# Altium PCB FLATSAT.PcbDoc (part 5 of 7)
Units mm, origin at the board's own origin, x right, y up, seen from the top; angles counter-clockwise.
Board outline 430 x 350 mm, 5 copper layers (Top Layer, Internal Plane 1, Internal Plane 2, DELETEME, Bottom Layer); 808 components, 852 nets, 6407 pads, 939 vias.
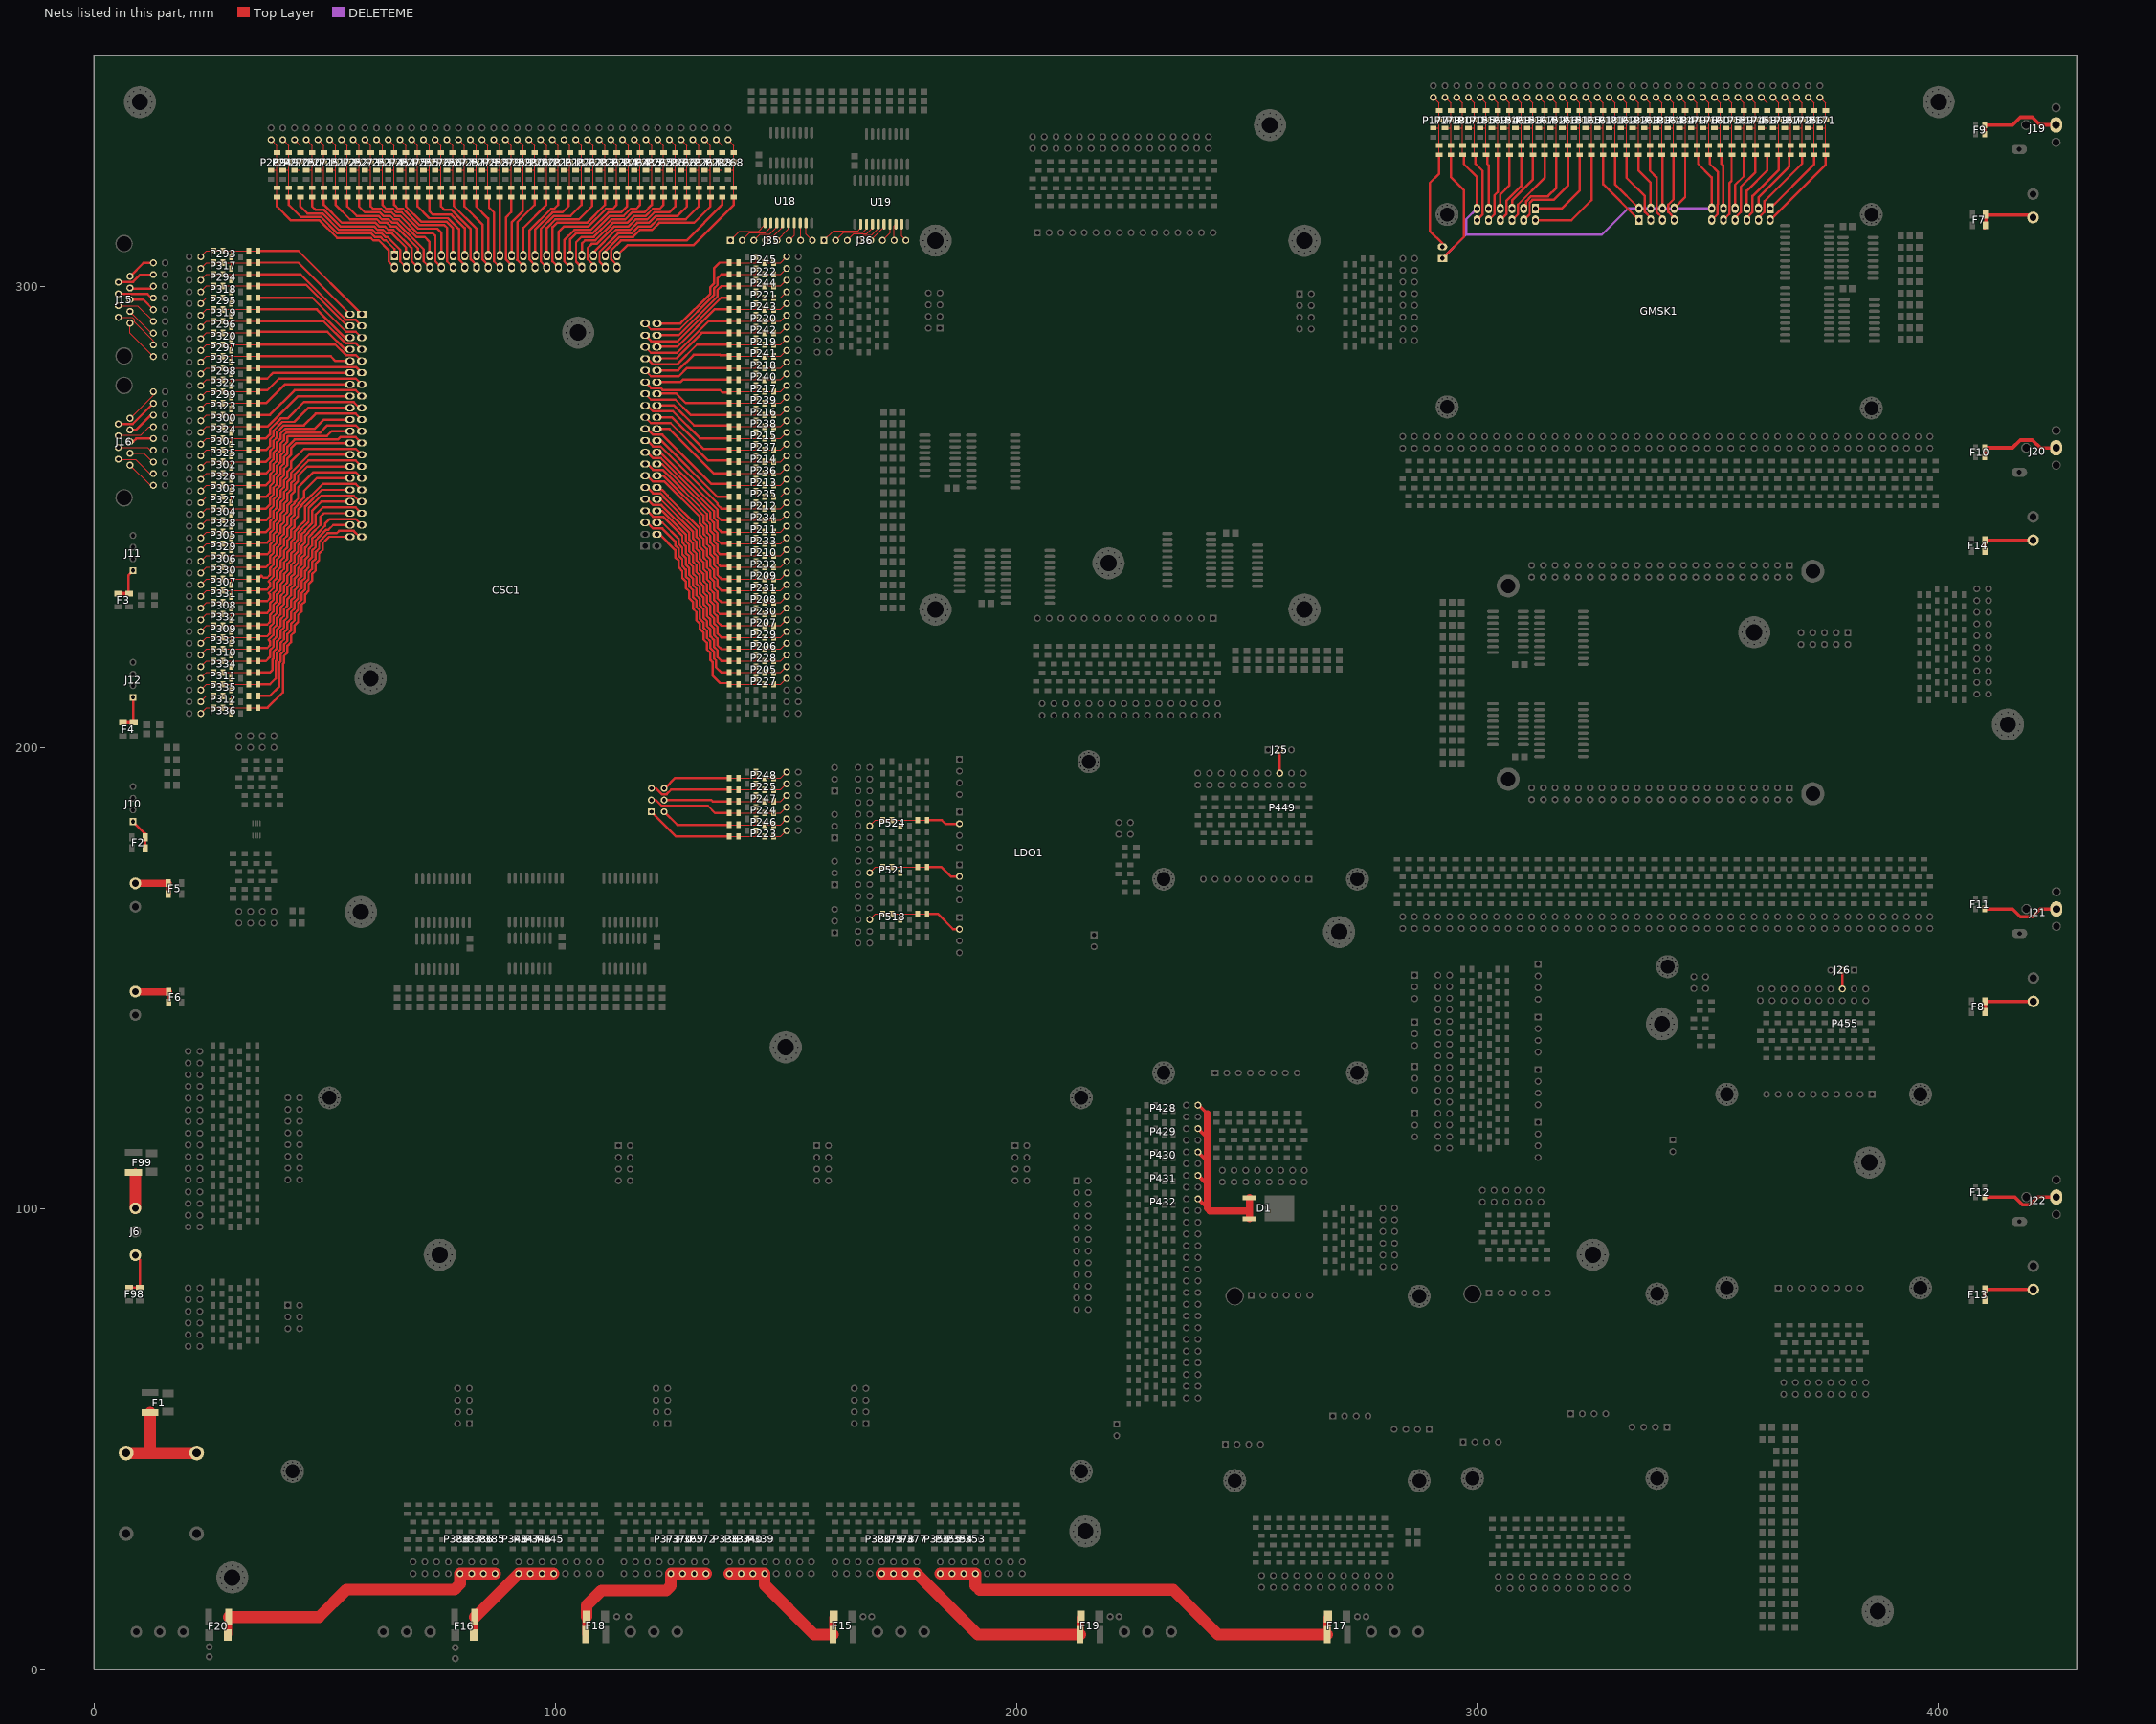
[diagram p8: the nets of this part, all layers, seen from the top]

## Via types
v1: diameter 1.016, hole 0.508, Top Layer to Bottom Layer, 541 vias
v2: diameter 0.6, hole 0.3, Top Layer to Bottom Layer, 214 vias
v3: diameter 1.27, hole 0.711, Top Layer to Bottom Layer, 147 vias
v4: diameter 0.8, hole 0.5, Top Layer to Bottom Layer, 31 vias
v5: diameter 0.5, hole 0.3, Top Layer to Bottom Layer, tented bottom, 5 vias
v6: diameter 1.27, hole 0.635, Top Layer to Bottom Layer, tented both sides, 1 vias

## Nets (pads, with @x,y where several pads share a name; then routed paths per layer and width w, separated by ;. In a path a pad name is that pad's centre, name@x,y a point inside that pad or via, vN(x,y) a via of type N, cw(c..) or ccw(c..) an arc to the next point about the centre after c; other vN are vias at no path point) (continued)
NetCSC1_C1_4: CSC1.C1_4 P227.2 | length 40.4
  Top Layer w0.508: CSC1.C1_4@122.072,246.232 122.677,246.232 126.064,242.846 126.064,241.266 126.826,240.504 126.826,239.041 127.588,238.279 127.588,236.817 128.35,236.055 128.35,234.592 129.112,233.83 129.112,232.368 129.874,231.606 129.874,230.144 130.636,229.382 130.636,227.585 131.398,226.823 131.398,225.695 132.16,224.933 132.16,223.471 132.922,222.709 132.922,221.246 133.684,220.484 133.684,219.022 134.128,218.577 134.128,215.653 135.803,213.978 137.51,213.978 P227.2@137.764,213.724
NetCSC1_C1_5: CSC1.C1_5 P205.2 | length 42.5
  Top Layer w0.508: CSC1.C1_5@119.532,248.772 119.993,248.772 121.25,247.514 123.262,247.514 126.064,244.712 126.064,243.887 126.826,243.125 126.826,241.581 127.588,240.819 127.588,239.357 128.35,238.595 128.35,237.132 129.112,236.37 129.112,234.908 129.874,234.146 129.874,232.684 130.636,231.922 130.636,230.459 131.398,229.697 131.398,227.901 132.16,227.139 132.16,226.011 132.922,225.249 132.922,223.786 133.684,223.024 133.684,221.562 134.446,220.8 134.446,219.338 134.89,218.893 134.89,217.431 136.057,216.264 137.748,216.264 P205.2@137.764,216.264
NetCSC1_C1_6: CSC1.C1_6 P228.2 | length 38.2
  Top Layer w0.508: CSC1.C1_6@122.072,248.772 123.281,248.772 126.826,245.227 126.826,244.121 127.588,243.359 127.588,241.897 128.35,241.135 128.35,239.672 129.112,238.91 129.112,237.448 129.874,236.686 129.874,235.224 130.636,234.462 130.636,232.999 131.398,232.237 131.398,230.775 132.16,230.013 132.16,228.217 132.922,227.455 132.922,226.326 133.684,225.564 133.684,224.102 134.446,223.34 134.446,221.878 135.208,221.116 135.208,219.653 136.057,218.804 137.748,218.804 P228.2@137.764,218.804
NetCSC1_C1_7: CSC1.C1_7 P206.2 | length 40.1
  Top Layer w0.508: CSC1.C1_7@119.532,251.312 119.993,251.312 121.25,250.054 123.433,250.054 127.588,245.899 127.588,244.437 128.35,243.675 128.35,242.212 129.112,241.45 129.112,239.988 129.874,239.226 129.874,237.764 130.636,237.002 130.636,235.539 131.398,234.777 131.398,233.315 132.16,232.553 132.16,231.091 132.922,230.329 132.922,228.532 133.684,227.77 133.684,226.642 134.446,225.88 134.446,224.418 135.208,223.656 135.208,222.193 136.057,221.344 137.748,221.344 P206.2@137.764,221.344
NetCSC1_C1_8: CSC1.C1_8 P229.2 | length 35.6
  Top Layer w0.508: CSC1.C1_8@122.072,251.312 123.253,251.312 128.35,246.215 128.35,244.752 129.112,243.99 129.112,242.528 129.874,241.766 129.874,240.304 130.636,239.542 130.636,238.079 131.398,237.317 131.398,235.855 132.16,235.093 132.16,233.631 132.922,232.869 132.922,231.406 133.684,230.644 133.684,228.848 134.446,228.086 134.446,226.958 135.208,226.196 135.208,224.733 136.057,223.884 137.748,223.884 P229.2@137.764,223.884
NetCSC1_C1_9: CSC1.C1_9 P207.2 | length 36.9
  Top Layer w0.508: CSC1.C1_9@119.993,253.852 121.25,252.594 123.048,252.594 129.112,246.53 129.112,245.068 129.874,244.306 129.874,242.844 130.636,242.082 130.636,240.619 131.398,239.857 131.398,238.395 132.16,237.633 132.16,236.171 132.922,235.409 132.922,233.946 133.684,233.184 133.684,231.722 134.446,230.96 134.446,229.164 135.241,228.369 135.208,228.336 135.208,227.273 136.057,226.424 137.748,226.424 P207.2@137.764,226.424
NetCSC1_C1_10: CSC1.C1_10 P230.2 | length 33.1
  Top Layer w0.508: CSC1.C1_10@122.072,253.852 122.868,253.852 129.874,246.846 129.874,245.384 130.636,244.622 130.636,243.159 131.398,242.397 131.398,240.935 132.16,240.173 132.16,238.711 132.922,237.949 132.922,236.486 133.684,235.724 133.684,234.262 134.446,233.5 134.446,232.038 135.208,231.276 135.208,229.479 135.723,228.964 137.748,228.964 P230.2@137.764,228.964
NetCSC1_C1_11: CSC1.C1_11 P208.2 | length 34.7
  Top Layer w0.508: CSC1.C1_11@119.532,256.392 119.993,256.392 121.25,255.134 122.664,255.134 122.688,255.11 122.893,255.11 123.63,254.373 123.63,254.168 130.636,247.162 130.636,245.699 131.398,244.937 131.398,243.475 132.16,242.713 132.16,241.251 132.922,240.489 132.922,239.026 133.684,238.264 133.684,236.802 134.446,236.04 134.446,234.578 135.208,233.816 135.208,232.353 136.057,231.504 137.748,231.504 P208.2@137.764,231.504
NetCSC1_C1_12: CSC1.C1_12 P231.2 | length 30.2
  Top Layer w0.508: CSC1.C1_12@122.072,256.392 122.483,256.392 123.003,255.872 123.208,255.872 124.392,254.689 124.392,254.484 131.398,247.477 131.398,246.015 132.16,245.253 132.16,243.791 132.922,243.029 132.922,241.566 133.684,240.804 133.684,239.342 134.446,238.58 134.446,237.118 135.208,236.356 135.208,234.893 136.057,234.044 137.748,234.044 P231.2@137.764,234.044
NetCSC1_C1_13: CSC1.C1_13 P209.2 | length 32.6
  Top Layer w0.508: CSC1.C1_13@119.532,258.932 119.993,258.932 121.25,257.674 123.741,257.674 131.398,250.017 131.398,248.555 132.16,247.793 132.16,246.331 132.922,245.569 132.922,244.106 133.684,243.344 133.684,241.882 134.446,241.12 134.446,239.658 135.213,238.89 135.213,238.28 135.208,238.275 135.208,237.433 136.057,236.584 137.748,236.584 P209.2@137.764,236.584
NetCSC1_C1_14: CSC1.C1_14 P232.2 | length 28.2
  Top Layer w0.508: CSC1.C1_14@122.072,258.932 123.561,258.932 132.16,250.333 132.16,248.871 132.922,248.109 132.922,246.646 133.684,245.884 133.684,244.422 134.446,243.66 134.446,242.198 135.208,241.436 135.208,239.973 135.803,239.378 137.494,239.378 137.748,239.124 P232.2@137.764,239.124
NetCSC1_C1_15: CSC1.C1_15 P210.2 | length 29.9
  Top Layer w0.508: CSC1.C1_15@119.532,261.472 119.993,261.472 121.25,260.214 123.356,260.214 132.922,250.649 132.922,249.186 133.684,248.424 133.684,246.962 134.446,246.2 134.446,244.738 135.208,243.976 135.208,242.513 135.803,241.918 137.494,241.918 137.748,241.664 P210.2@137.764,241.664
NetCSC1_C1_16: CSC1.C1_16 P233.2 | length 25.4
  Top Layer w0.508: CSC1.C1_16@122.072,261.472 123.176,261.472 133.684,250.964 133.684,249.502 134.446,248.74 134.446,247.278 135.208,246.516 135.208,245.053 136.057,244.204 137.748,244.204 P233.2@137.764,244.204
NetCSC1_C1_17: CSC1.C1_17 P211.2 | length 27.1
  Top Layer w0.508: CSC1.C1_17@119.532,264.012 119.993,264.012 121.25,262.754 122.972,262.754 134.446,251.28 134.446,249.818 135.208,249.056 135.208,247.593 136.057,246.744 137.748,246.744 P211.2@137.764,246.744
NetCSC1_C1_18: CSC1.C1_18 P234.2 | length 22.6
  Top Layer w0.508: CSC1.C1_18@122.072,264.012 122.791,264.012 135.208,251.596 135.208,250.133 136.057,249.284 137.748,249.284 P234.2@137.764,249.284
NetCSC1_C1_19: CSC1.C1_19 P212.2 | length 24.9
  Top Layer w0.508: CSC1.C1_19@119.532,266.552 119.993,266.552 121.25,265.294 122.587,265.294 122.611,265.27 122.893,265.27 135.208,252.955 135.208,252.673 136.057,251.824 137.748,251.824 P212.2@137.764,251.824 137.51,252.078 P212.2@137.494,252.078
NetCSC1_C1_20: CSC1.C1_20 P235.2 | length 20.7
  Top Layer w0.508: CSC1.C1_20@122.072,266.552 123.02,266.552 135.208,254.364 137.748,254.364 P235.2@137.764,254.364
NetCSC1_C1_21: CSC1.C1_21 P213.2 | length 23.3
  Top Layer w0.508: CSC1.C1_21@119.532,269.092 119.993,269.092 121.25,267.834 123.262,267.834 133.938,257.158 137.51,257.158 P213.2@137.764,256.904
NetCSC1_C1_22: CSC1.C1_22 P236.2 | length 20
  Top Layer w0.508: CSC1.C1_22@122.072,269.092 124.805,269.092 134.453,259.444 137.748,259.444 P236.2@137.764,259.444 P236.2@137.51,259.698
NetCSC1_C1_23: CSC1.C1_23 P214.2 | length 22.2
  Top Layer w0.508: CSC1.C1_23@119.532,271.632 120.798,270.366 125.055,270.366 133.183,262.238 137.51,262.238 P214.2@137.764,261.984
NetCSC1_C1_24: CSC1.C1_24 P237.2 | length 18.6
  Top Layer w0.508: CSC1.C1_24@122.072,271.632 125.313,271.632 132.167,264.778 137.51,264.778 P237.2@137.764,264.524
NetCSC1_C1_25: CSC1.C1_25 P215.2 | length 21.2
  Top Layer w0.508: CSC1.C1_25@119.532,274.172 119.993,274.172 121.25,272.914 125.555,272.914 131.405,267.064 137.748,267.064 P215.2@137.764,267.064
NetCSC1_C1_26: CSC1.C1_26 P238.2 | length 17.6
  Top Layer w0.508: CSC1.C1_26@122.072,274.172 125.821,274.172 130.135,269.858 137.51,269.858 P238.2@137.764,269.604
NetCSC1_C1_27: CSC1.C1_27 P216.2 | length 20.1
  Top Layer w0.508: CSC1.C1_27@119.532,276.712 120.798,275.446 126.071,275.446 129.373,272.144 137.748,272.144 P216.2@137.764,272.144
NetCSC1_C1_28: CSC1.C1_28 P239.2 | length 16.6
  Top Layer w0.508: CSC1.C1_28@122.072,276.712 122.154,276.795 126.246,276.795 128.357,274.684 137.748,274.684 P239.2@137.764,274.684
NetCSC1_C1_29: CSC1.C1_29 P217.2 | length 19.2
  Top Layer w0.508: CSC1.C1_29@119.532,279.252 120.814,277.97 122.893,277.97 123.306,277.557 135.724,277.557 136.24,277.041 137.565,277.041 137.748,277.224 P217.2@137.764,277.224
NetCSC1_C1_30: CSC1.C1_30 P240.2 | length 16.3
  Top Layer w0.508: CSC1.C1_30@122.072,279.252 127.196,279.252 127.708,279.764 137.748,279.764 P240.2@137.764,279.764 P240.2@137.51,280.018
NetCSC1_C1_31: CSC1.C1_31 P218.2 | length 19.5
  Top Layer w0.508: CSC1.C1_31@119.532,281.792 120.79,280.534 126.834,280.534 128.604,282.304 137.748,282.304 P218.2@137.764,282.304
NetCSC1_C1_32: CSC1.C1_32 P241.2 | length 17.2
  Top Layer w0.508: CSC1.C1_32@122.072,281.792 126.688,281.792 130.064,285.169 135.732,285.169 135.803,285.098 137.51,285.098 P241.2@137.764,284.844
NetCSC1_C1_33: CSC1.C1_33 P219.2 | length 20.5
  Top Layer w0.508: CSC1.C1_33@119.532,284.332 119.993,284.332 121.25,283.074 126.446,283.074 130.756,287.384 137.748,287.384 P219.2@137.764,287.384
NetCSC1_C1_34: CSC1.C1_34 P242.2 | length 18
  Top Layer w0.508: CSC1.C1_34@122.072,284.332 122.154,284.415 126.324,284.415 131.833,289.924 137.748,289.924 P242.2@137.764,289.924
NetCSC1_C1_35: CSC1.C1_35 P220.2 | length 21.6
  Top Layer w0.508: CSC1.C1_35@119.532,286.872 120.79,285.614 126.446,285.614 133.296,292.464 137.748,292.464 P220.2@137.764,292.464
NetCSC1_C1_36: CSC1.C1_36 P243.2 | length 19.1
  Top Layer w0.508: CSC1.C1_36@122.072,286.872 122.142,286.943 126.497,286.943 134.558,295.004 137.748,295.004 P243.2@137.764,295.004
NetCSC1_C1_37: CSC1.C1_37 P221.2 | length 22.7
  Top Layer w0.508: CSC1.C1_37@119.532,289.412 120.814,288.13 126.607,288.13 136.02,297.544 137.748,297.544 P221.2@137.764,297.544
NetCSC1_C1_38: CSC1.C1_38 P244.2 | length 20.9
  Top Layer w0.508: CSC1.C1_38@122.072,289.412 126.811,289.412 135.208,297.809 135.208,299.235 136.057,300.084 137.748,300.084 P244.2@137.764,300.084
NetCSC1_C1_39: CSC1.C1_39 P222.2 | length 25.4
  Top Layer w0.508: CSC1.C1_39@119.532,291.952 120.79,290.694 127.015,290.694 134.446,298.125 134.446,299.55 135.208,300.312 135.208,301.775 136.057,302.624 137.748,302.624 P222.2@137.764,302.624
NetCSC1_C1_40: CSC1.C1_40 P245.2 | length 23.9
  Top Layer w0.508: CSC1.C1_40@122.072,291.952 127.196,291.952 133.684,298.44 133.684,299.866 134.446,300.628 134.446,303.894 135.716,305.164 137.748,305.164 P245.2@137.764,305.164
NetCSC1_C2_1: CSC1.C2_1 P249.2 | length 30
  Top Layer w0.508: P249.2@42.244,319.404 42.244,319.388 42.244,317.697 44.871,315.07 49.258,315.07 52.814,311.514 60.126,311.514 60.888,310.752 62.118,310.752 62.88,309.99 63.311,309.99 65.176,308.125 CSC1.C2_1@65.176,306.684
NetCSC1_C2_2: CSC1.C2_2 P269.2 | length 34.4
  Top Layer w0.508: P269.2@39.704,319.404 39.704,319.388 39.704,317.356 42.752,314.308 48.943,314.308 52.753,310.498 60.064,310.498 60.572,309.99 61.802,309.99 63.918,307.874 63.918,305.424 65.176,304.166 CSC1.C2_2@65.176,304.144
NetCSC1_C2_3: CSC1.C2_3 P250.2 | length 27.9
  Top Layer w0.508: P250.2@47.324,319.388 47.324,317.356 48.086,316.594 49.89,316.594 53.446,313.038 60.757,313.038 61.519,312.276 62.749,312.276 63.511,311.514 64.624,311.514 67.716,308.423 CSC1.C2_3@67.716,306.684
NetCSC1_C2_4: CSC1.C2_4 P270.2 | length 31.9
  Top Layer w0.508: P270.2@44.784,319.388 44.784,317.356 46.308,315.832 49.574,315.832 53.13,312.276 60.442,312.276 61.204,311.514 62.433,311.514 63.195,310.752 63.626,310.752 66.434,307.945 66.434,305.426 CSC1.C2_4@67.716,304.144
NetCSC1_C2_5: CSC1.C2_5 P251.2 | length 25
  Top Layer w0.508: P251.2@52.404,319.388 52.404,317.697 55.539,314.562 61.389,314.562 62.151,313.8 63.613,313.8 64.375,313.038 65.471,313.038 70.256,308.253 CSC1.C2_5@70.256,306.684
NetCSC1_C2_6: CSC1.C2_6 P271.2 | length 29.4
  Top Layer w0.508: P271.2@49.864,319.404 49.864,319.388 49.864,317.697 53.761,313.8 61.073,313.8 61.835,313.038 63.065,313.038 63.827,312.276 64.94,312.276 68.974,308.242 68.974,305.426 CSC1.C2_6@70.256,304.144
NetCSC1_C2_7: CSC1.C2_7 P252.2 | length 23.5
  Top Layer w0.508: P252.2@57.484,319.388 57.484,317.356 58.754,316.086 62.02,316.086 62.782,315.324 64.244,315.324 65.006,314.562 66.102,314.562 69.912,310.752 71.708,310.752 72.796,309.664 CSC1.C2_7@72.796,306.684
NetCSC1_C2_8: CSC1.C2_8 P272.2 | length 26.9
  Top Layer w0.508: P272.2@54.944,319.388 54.944,317.356 56.976,315.324 61.704,315.324 62.466,314.562 63.929,314.562 64.691,313.8 65.786,313.8 71.514,308.073 71.514,305.426 CSC1.C2_8@72.796,304.144
NetCSC1_C2_9: CSC1.C2_9 P253.2 | length 22
  Top Layer w0.508: P253.2@62.564,319.388 62.564,317.61 62.651,317.61 63.413,316.848 64.876,316.848 65.638,316.086 66.733,316.086 70.289,312.53 74.502,312.53 75.336,311.696 CSC1.C2_9@75.336,306.684
NetCSC1_C2_10: CSC1.C2_10 P273.2 | length 26.1
  Top Layer w0.508: P273.2@60.024,319.404 60.024,319.388 60.024,317.356 60.532,316.848 62.336,316.848 63.098,316.086 64.56,316.086 65.322,315.324 66.418,315.324 70.228,311.514 73.486,311.514 74.054,310.946 74.054,305.426 CSC1.C2_10@75.336,304.144
NetCSC1_C2_11: CSC1.C2_11 P254.2 | length 20.2
  Top Layer w0.508: P254.2@67.644,319.388 67.644,317.356 70.946,314.054 76.472,314.054 77.876,312.651 CSC1.C2_11@77.876,306.684
NetCSC1_C2_12: CSC1.C2_12 P274.2 | length 24.4
  Top Layer w0.508: P274.2@65.104,319.388 65.104,317.697 65.953,316.848 67.049,316.848 67.811,316.086 67.836,316.086 70.63,313.292 76.026,313.292 76.594,312.724 76.594,305.426 CSC1.C2_12@77.876,304.144
NetCSC1_C2_13: CSC1.C2_13 P255.2 | length 18.2
  Top Layer w0.508: P255.2@72.724,319.388 72.724,316.34 73.486,315.578 77.488,315.578 80.416,312.651 CSC1.C2_13@80.416,306.684
NetCSC1_C2_14: CSC1.C2_14 P275.2 | length 21.9
  Top Layer w0.508: P275.2@70.184,319.404 70.184,319.388 70.184,317.356 72.724,314.816 76.788,314.816 79.158,312.446 79.158,305.863 80.416,304.605 CSC1.C2_14@80.416,304.144
NetCSC1_C2_15: CSC1.C2_15 P256.2 | length 14.8
  Top Layer w0.508: P256.2@77.804,319.388 78.058,319.134 78.058,317.443 82.956,312.546 CSC1.C2_15@82.956,306.684
NetCSC1_C2_16: CSC1.C2_16 P276.2 | length 19.3
  Top Layer w0.508: P276.2@75.264,319.388 75.264,317.356 76.026,316.594 77.55,316.594 81.698,312.446 81.698,305.863 82.956,304.605 CSC1.C2_16@82.956,304.144
NetCSC1_C2_17: CSC1.C2_17 P257.2 | length 13.8
  Top Layer w0.508: P257.2@82.884,319.388 82.884,317.356 85.496,314.744 CSC1.C2_17@85.496,306.684
NetCSC1_C2_18: CSC1.C2_18 P277.2 | length 17.4
  Top Layer w0.508: P277.2@80.344,319.404 80.344,319.388 80.344,317.356 84.238,313.462 84.238,305.863 85.496,304.605 CSC1.C2_18@85.496,304.144
NetCSC1_C2_19: CSC1.C2_19 P258.2 | length 12.7
  Top Layer w0.508: P258.2@87.964,319.404 88.036,319.332 CSC1.C2_19@88.036,306.684
NetCSC1_C2_20: CSC1.C2_20 P278.2 | length 16.3
  Top Layer w0.508: P278.2@85.424,319.388 85.678,319.134 85.678,317.102 86.754,316.026 86.754,305.426 CSC1.C2_20@88.036,304.144
NetCSC1_C2_21: CSC1.C2_21 P259.2 | length 13.7
  Top Layer w0.508: CSC1.C2_21@90.576,306.684 90.576,313.872 93.044,316.34 P259.2@93.044,319.388
NetCSC1_C2_22: CSC1.C2_22 P279.2 | length 16.3
  Top Layer w0.508: P279.2@90.504,319.404 90.504,319.388 90.504,316.136 89.318,314.949 89.318,305.863 90.576,304.605 CSC1.C2_22@90.576,304.144
NetCSC1_C2_23: CSC1.C2_23 P260.2 | length 14.8
  Top Layer w0.508: CSC1.C2_23@93.116,306.684 93.116,312.689 98.124,317.697 P260.2@98.124,319.388
NetCSC1_C2_24: CSC1.C2_24 P280.2 | length 17.4
  Top Layer w0.508: CSC1.C2_24@93.116,304.144 93.116,304.402 91.774,305.744 91.834,305.803 91.834,313.947 95.584,317.697 95.584,319.388 P280.2@95.584,319.404
NetCSC1_C2_25: CSC1.C2_25 P261.2 | length 17.1
  Top Layer w0.508: CSC1.C2_25@95.656,306.684 95.656,312.286 99.456,316.086 101.593,316.086 102.95,317.443 102.95,319.15 P261.2@103.204,319.404
NetCSC1_C2_26: CSC1.C2_26 P281.2 | length 18.8
  Top Layer w0.508: CSC1.C2_26@95.656,304.144 95.656,304.605 94.398,305.863 94.398,312.106 99.14,316.848 99.815,316.848 100.664,317.697 100.664,319.388 P281.2@100.664,319.404
NetCSC1_C2_27: CSC1.C2_27 P262.2 | length 19.9
  Top Layer w0.508: CSC1.C2_27@98.196,306.684 98.196,312.671 100.087,314.562 105.149,314.562 108.03,317.443 108.03,319.15 P262.2@108.284,319.404
NetCSC1_C2_28: CSC1.C2_28 P282.2 | length 21.6
  Top Layer w0.508: CSC1.C2_28@98.196,304.144 96.914,305.426 96.914,312.466 99.771,315.324 103.371,315.324 105.744,317.697 105.744,319.388 P282.2@105.744,319.404
NetCSC1_C2_29: CSC1.C2_29 P263.2 | length 21.9
  Top Layer w0.508: CSC1.C2_29@100.736,306.684 100.736,311.84 101.934,313.038 107.242,313.038 111.052,316.848 112.515,316.848 113.364,317.697 P263.2@113.364,319.388
NetCSC1_C2_30: CSC1.C2_30 P283.2 | length 24.3
  Top Layer w0.508: CSC1.C2_30@100.736,304.144 99.454,305.426 99.454,312.851 100.403,313.8 106.927,313.8 110.824,317.697 110.824,319.388 P283.2@110.824,319.404
NetCSC1_C2_31: CSC1.C2_31 P264.2 | length 23.5
  Top Layer w0.508: CSC1.C2_31@103.276,306.684 103.276,310.254 104.536,311.514 108.092,311.514 111.902,315.324 114.888,315.324 116.412,316.848 117.595,316.848 118.444,317.697 P264.2@118.444,319.388
NetCSC1_C2_32: CSC1.C2_32 P284.2 | length 25.2
  Top Layer w0.508: CSC1.C2_32@103.276,304.144 101.994,305.426 101.994,310.05 104.22,312.276 107.776,312.276 111.586,316.086 114.293,316.086 115.65,317.443 115.65,319.15 P284.2@115.904,319.404
NetCSC1_C2_33: CSC1.C2_33 P265.2 | length 25.5
  Top Layer w0.508: CSC1.C2_33@105.816,306.684 105.816,309.3 106.506,309.99 108.723,309.99 112.533,313.8 115.65,313.8 117.174,315.324 119.688,315.324 121.212,316.848 122.675,316.848 123.524,317.697 P265.2@123.524,319.388
NetCSC1_C2_34: CSC1.C2_34 P285.2 | length 27.4
  Top Layer w0.508: CSC1.C2_34@105.816,304.144 104.558,305.402 104.558,309.566 105.744,310.752 108.407,310.752 112.217,314.562 115.204,314.562 116.728,316.086 119.373,316.086 120.984,317.697 120.984,319.388 P285.2@120.984,319.404
NetCSC1_C2_35: CSC1.C2_35 P266.2 | length 27.2
  Top Layer w0.508: CSC1.C2_35@108.356,306.684 108.356,307.467 113.164,312.276 116.281,312.276 117.805,313.8 120.32,313.8 121.844,315.324 126.572,315.324 128.604,317.356 P266.2@128.604,319.388
NetCSC1_C2_36: CSC1.C2_36 P286.2 | length 29.5
  Top Layer w0.508: CSC1.C2_36@108.356,304.144 108.356,304.605 107.098,305.863 107.098,308.382 107.943,309.228 109.039,309.228 112.849,313.038 115.966,313.038 117.49,314.562 120.004,314.562 121.528,316.086 124.794,316.086 126.064,317.356 P286.2@126.064,319.388
NetCSC1_C2_37: CSC1.C2_37 P267.2 | length 29.8
  Top Layer w0.508: CSC1.C2_37@110.896,306.684 110.896,307.686 113.962,310.752 116.913,310.752 118.437,312.276 121.046,312.276 122.57,313.8 130.128,313.8 133.684,317.356 P267.2@133.684,319.388
NetCSC1_C2_38: CSC1.C2_38 P287.2 | length 31.5
  Top Layer w0.508: CSC1.C2_38@110.896,304.144 109.638,305.402 109.638,307.505 113.646,311.514 116.597,311.514 118.121,313.038 120.73,313.038 122.254,314.562 128.35,314.562 131.144,317.356 131.144,319.388 P287.2@131.144,319.404
NetCSC1_C2_39: CSC1.C2_39 P268.2 | length 31.6
  Top Layer w0.508: CSC1.C2_39@113.436,306.684 115.725,308.974 130.041,308.974 138.764,317.697 P268.2@138.764,319.388
NetCSC1_C2_40: CSC1.C2_40 P288.2 | length 34.1
  Top Layer w0.508: CSC1.C2_40@113.436,304.144 113.436,304.605 112.178,305.863 112.178,307.874 114.278,309.974 128.501,309.974 136.224,317.697 136.224,319.388 P288.2@136.224,319.404
NetCSC1_C3_1: CSC1.C3_1 P293.2 | length 28.1
  Top Layer w0.508: P293.2@35.624,307.704 35.64,307.704 44.344,307.704 CSC1.C3_1@58.064,293.984
NetCSC1_C3_2: CSC1.C3_2 P317.2 | length 24.5
  Top Layer w0.508: P317.2@35.624,305.164 35.64,305.164 44.344,305.164 CSC1.C3_2@55.524,293.984
NetCSC1_C3_3: CSC1.C3_3 P294.2 | length 27.1
  Top Layer w0.508: P294.2@35.624,302.624 35.64,302.624 44.805,302.624 54.702,292.726 56.782,292.726 CSC1.C3_3@58.064,291.444
NetCSC1_C3_4: CSC1.C3_4 P318.2 | length 23.7
  Top Layer w0.508: P318.2@35.624,300.084 35.878,300.338 46.013,300.338 54.907,291.444 CSC1.C3_4@55.524,291.444
NetCSC1_C3_5: CSC1.C3_5 P295.2 | length 26
  Top Layer w0.508: P295.2@35.624,297.544 35.64,297.544 47.345,297.544 54.702,290.186 56.782,290.186 CSC1.C3_5@58.064,288.904
NetCSC1_C3_6: CSC1.C3_6 P319.2 | length 22.4
  Top Layer w0.508: P319.2@35.624,295.004 35.64,295.004 48.34,295.004 54.44,288.904 CSC1.C3_6@55.524,288.904
NetCSC1_C3_7: CSC1.C3_7 P296.2 | length 25
  Top Layer w0.508: P296.2@35.624,292.464 35.64,292.464 49.802,292.464 54.62,287.646 56.782,287.646 CSC1.C3_7@58.064,286.364
NetCSC1_C3_8: CSC1.C3_8 P320.2 | length 21.6
  Top Layer w0.508: P320.2@35.624,289.924 35.878,290.178 50.626,290.178 54.44,286.364 CSC1.C3_8@55.524,286.364
NetCSC1_C3_9: CSC1.C3_9 P297.2 | length 23.9
  Top Layer w0.508: P297.2@35.624,287.384 35.64,287.384 52.342,287.384 54.62,285.106 56.782,285.106 CSC1.C3_9@58.064,283.824
NetCSC1_C3_10: CSC1.C3_10 P321.2 | length 20.3
  Top Layer w0.508: P321.2@35.624,284.844 35.64,284.844 51.388,284.844 52.408,283.824 CSC1.C3_10@55.524,283.824
NetCSC1_C3_11: CSC1.C3_11 P298.2 | length 23.1
  Top Layer w0.508: P298.2@35.624,282.304 35.64,282.304 35.878,282.542 56.806,282.542 CSC1.C3_11@58.064,281.284
NetCSC1_C3_12: CSC1.C3_12 P322.2 | length 20.5
  Top Layer w0.508: P322.2@35.624,279.764 35.878,280.018 37.585,280.018 38.851,281.284 CSC1.C3_12@55.524,281.284
NetCSC1_C3_13: CSC1.C3_13 P299.2 | length 24.1
  Top Layer w0.508: P299.2@35.624,277.224 35.878,277.478 37.585,277.478 40.109,280.002 56.806,280.002 CSC1.C3_13@58.064,278.744
NetCSC1_C3_14: CSC1.C3_14 P323.2 | length 21.6
  Top Layer w0.508: P323.2@35.624,274.684 37.331,274.684 41.391,278.744 CSC1.C3_14@55.524,278.744
NetCSC1_C3_15: CSC1.C3_15 P300.2 | length 25.2
  Top Layer w0.508: P300.2@35.624,272.144 35.64,272.144 38.18,272.144 43.514,277.478 56.79,277.478 CSC1.C3_15@58.064,276.204
NetCSC1_C3_16: CSC1.C3_16 P324.2 | length 22.6
  Top Layer w0.508: P324.2@35.624,269.604 35.64,269.604 37.672,269.604 44.272,276.204 CSC1.C3_16@55.524,276.204
NetCSC1_C3_17: CSC1.C3_17 P301.2 | length 26.9
  Top Layer w0.508: P301.2@35.624,267.064 35.64,267.064 37.331,267.064 38.18,267.913 38.18,269.019 40.539,271.378 41.986,271.378 45.53,274.922 56.345,274.922 57.603,273.664 CSC1.C3_17@58.064,273.664
NetCSC1_C3_18: CSC1.C3_18 P325.2 | length 25.2
  Top Layer w0.508: P325.2@35.624,264.524 37.331,264.524 38.18,265.373 38.18,266.836 38.942,267.598 38.942,268.704 40.854,270.616 43.423,270.616 46.471,273.664 CSC1.C3_18@55.524,273.664
NetCSC1_C3_19: CSC1.C3_19 P302.2 | length 29.6
  Top Layer w0.508: P302.2@35.624,261.984 35.64,261.984 37.331,261.984 38.18,262.833 38.18,264.296 38.942,265.058 38.942,266.52 39.704,267.282 39.704,268.388 41.17,269.854 45.542,269.854 48.086,272.398 56.79,272.398 CSC1.C3_19@58.064,271.124
NetCSC1_C3_20: CSC1.C3_20 P326.2 | length 28
  Top Layer w0.508: P326.2@35.624,259.444 35.64,259.444 37.331,259.444 38.18,260.293 38.18,261.756 38.942,262.518 38.942,263.98 39.704,264.742 39.704,266.204 40.466,266.966 40.466,268.072 41.486,269.092 47.828,269.092 49.86,271.124 CSC1.C3_20@55.524,271.124
NetCSC1_C3_21: CSC1.C3_21 P303.2 | length 32.4
  Top Layer w0.508: P303.2@35.624,256.904 35.64,256.904 37.331,256.904 38.18,257.753 38.18,259.216 38.942,259.978 38.942,261.44 39.704,262.202 39.704,263.664 40.466,264.426 40.466,265.889 41.228,266.651 41.228,267.757 41.801,268.33 49.098,268.33 50.626,269.858 56.79,269.858 CSC1.C3_21@58.064,268.584
NetCSC1_C3_22: CSC1.C3_22 P327.2 | length 30.7
  Top Layer w0.508: P327.2@35.624,254.364 35.64,254.364 37.331,254.364 38.18,255.213 38.18,256.676 38.942,257.438 38.942,258.9 39.704,259.662 39.704,261.124 40.466,261.886 40.466,263.349 41.228,264.111 41.228,265.573 41.99,266.335 41.99,267.441 42.117,267.568 50.535,267.568 51.551,268.584 CSC1.C3_22@55.524,268.584
NetCSC1_C3_23: CSC1.C3_23 P304.2 | length 34.5
  Top Layer w0.508: P304.2@35.624,251.824 35.64,251.824 37.331,251.824 38.18,252.673 38.18,254.136 38.942,254.898 38.942,256.36 39.704,257.122 39.704,258.584 40.466,259.346 40.466,260.809 41.228,261.571 41.228,263.033 41.99,263.795 41.99,265.257 43.539,266.806 52.908,266.806 53.42,267.318 56.79,267.318 CSC1.C3_23@58.064,266.044
NetCSC1_C3_24: CSC1.C3_24 P328.2 | length 32.8
  Top Layer w0.508: P328.2@35.624,249.284 35.64,249.284 37.331,249.284 38.18,250.133 38.18,251.596 38.942,252.358 38.942,253.82 39.704,254.582 39.704,256.044 40.466,256.806 40.466,258.269 41.228,259.031 41.228,260.493 41.99,261.255 41.99,262.717 42.752,263.479 42.752,264.942 43.854,266.044 CSC1.C3_24@55.524,266.044
NetCSC1_C3_25: CSC1.C3_25 P305.2 | length 36.2
  Top Layer w0.508: P305.2@35.624,246.744 35.64,246.744 37.331,246.744 38.18,247.593 38.18,249.056 38.942,249.818 38.942,251.28 39.704,252.042 39.704,253.504 40.466,254.266 40.466,255.729 41.228,256.491 41.228,257.953 41.99,258.715 41.99,259.883 42.752,260.645 42.752,261.984 45.53,264.762 56.806,264.762 CSC1.C3_25@58.064,263.504
NetCSC1_C3_26: CSC1.C3_26 P329.2 | length 33.7
  Top Layer w0.508: P329.2@35.624,244.204 35.64,244.204 35.868,244.204 36.122,244.458 37.585,244.458 38.18,245.053 38.18,246.516 38.942,247.278 38.942,248.74 39.704,249.502 39.704,250.964 40.466,251.726 40.466,253.189 41.228,253.951 41.228,255.413 41.99,256.175 41.99,257.637 42.752,258.399 42.752,259.567 46.689,263.504 CSC1.C3_26@55.524,263.504
NetCSC1_C3_27: CSC1.C3_27 P306.2 | length 38.2
  Top Layer w0.508: P306.2@35.624,241.664 35.64,241.664 35.894,241.918 37.585,241.918 38.18,242.513 38.18,243.976 38.942,244.738 38.942,246.2 39.704,246.962 39.704,248.424 40.466,249.186 40.466,250.649 41.228,251.411 41.228,252.873 41.99,253.635 41.99,255.097 42.752,255.859 42.752,257.322 43.514,258.084 43.514,259.252 46.5,262.238 56.79,262.238 CSC1.C3_27@58.064,260.964
NetCSC1_C3_28: CSC1.C3_28 P330.2 | length 36.5
  Top Layer w0.508: P330.2@35.624,239.124 35.64,239.124 37.331,239.124 38.18,239.973 38.18,241.436 38.942,242.198 38.942,243.66 39.704,244.422 39.704,245.884 40.466,246.646 40.466,248.109 41.228,248.871 41.228,250.333 41.99,251.095 41.99,252.557 42.752,253.319 42.752,254.782 43.514,255.544 43.514,257.006 44.276,257.768 44.276,258.936 46.304,260.964 CSC1.C3_28@55.524,260.964
NetCSC1_C3_29: CSC1.C3_29 P307.2 | length 40.4
  Top Layer w0.508: P307.2@35.624,236.584 35.64,236.584 36.275,237.219 36.362,237.219 36.743,236.838 37.585,236.838 38.18,237.433 38.18,238.896 38.942,239.658 38.942,241.12 39.704,241.882 39.704,243.344 40.466,244.106 40.466,245.569 41.228,246.331 41.228,247.793 41.99,248.555 41.99,250.017 42.752,250.779 42.752,252.242 43.514,253.004 43.514,253.217 44.276,253.979 44.276,256.396 47.578,259.698 56.79,259.698 CSC1.C3_29@58.064,258.424
NetCSC1_C3_30: CSC1.C3_30 P331.2 | length 38.1
  Top Layer w0.508: P331.2@35.624,234.044 35.64,234.044 35.894,234.298 37.585,234.298 38.18,234.893 38.18,235.735 37.9,236.014 37.9,236.076 38.942,237.118 38.942,238.58 39.704,239.342 39.704,240.804 40.466,241.566 40.466,243.029 41.228,243.791 41.228,245.253 41.99,246.015 41.99,247.477 42.752,248.239 42.752,249.702 43.514,250.464 43.514,251.926 44.276,252.688 44.276,252.902 45.546,254.172 45.546,255.634 48.336,258.424 CSC1.C3_30@55.524,258.424
NetCSC1_C3_31: CSC1.C3_31 P308.2 | length 41.7
  Top Layer w0.508: P308.2@35.624,231.504 35.64,231.504 35.894,231.758 37.585,231.758 38.18,232.353 38.18,233.195 37.9,233.474 37.9,233.536 38.942,234.578 38.942,236.04 39.704,236.802 39.704,238.264 40.466,239.026 40.466,240.489 41.228,241.251 41.228,242.713 41.99,243.475 41.99,244.937 42.752,245.699 42.752,247.162 43.514,247.924 43.514,249.386 44.276,250.148 44.276,251.61 45.038,252.372 45.038,252.586 49.61,257.158 56.79,257.158 CSC1.C3_31@58.064,255.884
NetCSC1_C3_32: CSC1.C3_32 P332.2 | length 39.7
  Top Layer w0.508: P332.2@35.624,228.964 35.878,229.218 37.585,229.218 38.18,229.813 38.18,231.276 38.942,232.038 38.942,233.5 39.704,234.262 39.704,235.724 40.466,236.486 40.466,237.949 41.228,238.711 41.228,240.173 41.99,240.935 41.99,242.397 42.752,243.159 42.752,244.622 43.514,245.384 43.514,246.846 44.276,247.608 44.276,247.745 45.8,249.269 45.8,252.27 49.414,255.884 CSC1.C3_32@55.524,255.884
NetCSC1_C3_33: CSC1.C3_33 P309.2 | length 44.2
  Top Layer w0.508: P309.2@35.624,226.424 35.64,226.424 35.868,226.424 36.122,226.678 37.585,226.678 38.18,227.273 38.18,228.736 38.942,229.498 38.942,230.96 39.704,231.722 39.704,233.184 40.466,233.946 40.466,235.409 41.228,236.171 41.228,237.633 41.99,238.395 41.99,239.857 42.752,240.619 42.752,242.082 43.514,242.844 43.514,244.306 44.276,245.068 44.276,246.53 45.038,247.292 45.038,247.429 46.562,248.953 46.562,251.909 49.255,254.602 56.345,254.602 57.603,253.344 CSC1.C3_33@58.064,253.344
NetCSC1_C3_34: CSC1.C3_34 P333.2 | length 42.3
  Top Layer w0.508: P333.2@35.624,223.884 35.878,224.138 37.585,224.138 38.18,224.733 38.18,226.196 38.942,226.958 38.942,228.42 39.704,229.182 39.704,230.644 40.466,231.406 40.466,232.869 41.228,233.631 41.228,235.093 41.99,235.855 41.99,237.317 42.752,238.079 42.752,239.542 43.514,240.304 43.514,241.766 44.276,242.528 44.276,243.99 45.038,244.752 45.038,246.215 45.8,246.977 45.8,247.114 47.324,248.638 47.324,251.316 49.352,253.344 CSC1.C3_34@55.524,253.344
NetCSC1_C3_35: CSC1.C3_35 P310.2 | length 46.7
  Top Layer w0.508: P310.2@35.624,221.344 35.64,221.344 35.894,221.598 37.585,221.598 38.18,222.193 38.18,223.035 37.9,223.314 37.9,223.376 38.942,224.418 38.942,225.88 39.704,226.642 39.704,228.104 40.466,228.866 40.466,230.329 41.228,231.091 41.228,232.553 41.99,233.315 41.99,234.777 42.752,235.539 42.752,237.002 43.514,237.764 43.514,239.226 44.276,239.988 44.276,241.45 45.038,242.212 45.038,243.675 45.8,244.437 45.8,245.899 46.562,246.661 46.562,246.798 48.086,248.322 48.086,250.554 49.61,252.078 56.79,252.078 CSC1.C3_35@58.064,250.804
NetCSC1_C3_36: CSC1.C3_36 P334.2 | length 44.6
  Top Layer w0.508: P334.2@35.624,218.804 35.64,218.804 37.331,218.804 38.18,219.653 38.18,221.116 38.942,221.878 38.942,223.34 39.704,224.102 39.704,225.564 40.466,226.326 40.466,227.789 41.228,228.551 41.228,230.013 41.99,230.775 41.99,232.237 42.752,232.999 42.752,234.462 43.514,235.224 43.514,236.686 44.276,237.448 44.276,238.91 45.038,239.672 45.038,241.135 45.8,241.897 45.8,243.359 46.562,244.121 46.562,245.584 47.324,246.346 47.324,246.482 49.102,248.26 49.102,250.046 49.86,250.804 CSC1.C3_36@55.524,250.804
NetCSC1_C3_37: CSC1.C3_37 P311.2 | length 48.7
  Top Layer w0.508: P311.2@35.624,216.264 35.64,216.264 38.18,216.264 38.688,216.772 38.688,219.084 38.942,219.338 38.942,220.8 39.704,221.562 39.704,223.024 40.466,223.786 40.466,225.249 41.228,226.011 41.228,227.473 41.99,228.235 41.99,229.697 42.752,230.459 42.752,231.922 43.514,232.684 43.514,234.146 44.276,234.908 44.276,236.37 45.038,237.132 45.038,238.595 45.8,239.357 45.8,240.819 46.562,241.581 46.562,243.044 47.324,243.806 47.324,245.268 48.086,246.03 50.118,248.062 50.118,248.522 51.134,249.538 56.79,249.538 CSC1.C3_37@58.064,248.264
NetCSC1_C3_38: CSC1.C3_38 P335.2 | length 46.7
  Top Layer w0.508: P335.2@35.624,213.724 35.64,213.724 38.18,213.724 39.45,214.994 39.45,218.768 39.704,219.022 39.704,220.484 40.466,221.246 40.466,222.709 41.228,223.471 41.228,224.933 41.99,225.695 41.99,227.157 42.752,227.919 42.752,229.382 43.514,230.144 43.514,231.606 44.276,232.368 44.276,233.83 45.038,234.592 45.038,236.055 45.8,236.817 45.8,238.279 46.562,239.041 46.562,240.504 47.324,241.266 47.324,242.728 48.086,243.49 48.086,244.952 48.848,245.714 50.382,247.248 50.876,247.248 51.892,248.264 CSC1.C3_38@55.524,248.264
NetCSC1_C3_39: CSC1.C3_39 P312.2 | length 51.1
  Top Layer w0.508: P312.2@35.624,211.184 35.64,211.184 38.118,211.184 40.212,213.278 40.212,218.452 40.466,218.706 40.466,220.169 41.228,220.931 41.228,222.393 41.99,223.155 41.99,224.617 42.752,225.379 42.752,226.842 43.514,227.604 43.514,229.066 44.276,229.828 44.276,231.29 45.038,232.052 45.038,233.515 45.8,234.277 45.8,235.739 46.562,236.501 46.562,237.964 47.324,238.726 47.324,240.188 48.086,240.95 48.086,242.412 48.848,243.174 48.848,244.637 49.61,245.399 50.698,246.486 52.686,246.486 53.182,246.982 56.345,246.982 57.603,245.724 CSC1.C3_39@58.064,245.724
NetCSC1_C3_40: CSC1.C3_40 P336.2 | length 49.2
  Top Layer w0.508: P336.2@35.624,208.644 35.64,208.644 37.672,208.644 40.974,211.946 40.974,218.137 41.228,218.391 41.228,219.853 41.99,220.615 41.99,222.077 42.752,222.839 42.752,224.302 43.514,225.064 43.514,226.526 44.276,227.288 44.276,228.75 45.038,229.512 45.038,230.975 45.8,231.737 45.8,233.199 46.562,233.961 46.562,235.424 47.324,236.186 47.324,237.648 48.086,238.41 48.086,239.872 48.848,240.634 48.848,242.097 49.61,242.859 49.61,244.321 50.372,245.083 51.013,245.724 CSC1.C3_40@55.524,245.724
NetCSC1_ISP1: CSC1.ISP1 P223.2 | length 19.1
  Top Layer w0.508: CSC1.ISP1@120.867,186.074 126.237,180.704 137.748,180.704 P223.2@137.764,180.704
NetCSC1_ISP2: CSC1.ISP2 P224.2 | length 18.1
  Top Layer w0.508: CSC1.ISP2@120.867,188.614 121.878,188.614 123.136,187.356 133.128,187.356 134.7,185.784 137.748,185.784 P224.2@137.764,185.784
NetCSC1_ISP3: CSC1.ISP3 P225.2 | length 17.8
  Top Layer w0.508: CSC1.ISP3@120.867,191.154 121.878,191.154 123.136,189.896 124.178,189.896 125.145,190.864 137.748,190.864 P225.2@137.764,190.864
NetCSC1_ISP4: CSC1.ISP4 P246.2 | length 15.3
  Top Layer w0.508: CSC1.ISP4@123.657,186.074 126.487,183.244 137.748,183.244 P246.2@137.764,183.244
NetCSC1_ISP5: CSC1.ISP5 P247.2 | length 14.2
  Top Layer w0.508: CSC1.ISP5@123.657,188.614 133.902,188.614 134.192,188.324 137.748,188.324 P247.2@137.764,188.324
NetCSC1_ISP6: CSC1.ISP6 P248.2 | length 14.9
  Top Layer w0.508: CSC1.ISP6@123.814,191.154 126.064,193.404 137.748,193.404 P248.2@137.764,193.404
NetD1_1: D1.1 P428.1 P429.1 P430.1 P431.1 P432.1 | length 49.6
  Top Layer w0.762: P432.1@239.399,102.116 241.427,100.088 ; P431.1@239.399,107.196 241.427,105.168 ; P430.1@239.399,112.276 241.427,110.248 241.675,110 ; P429.1@239.399,117.356 241.427,115.328 241.755,115 ; P428.1@239.399,122.436 239.564,122.436 241.427,120.573
  Top Layer w1.524: 241.427,120.573 241.427,115.328 241.427,110.248 241.427,105.168 241.427,100.088 242,99.515 250.598,99.515 ; D1.1@250.598,97.786 250.598,99.515 ; D1.1@250.598,102.366 250.598,99.515
NetF1_1: F1.1 J4.1 | length 24.1
  Top Layer w2.54: J4.1@7,47 12.197,47 ; F1.1@12.197,55.765 12.197,47 ; J4.1@22.3,47 12.197,47
NetF2_2: F2.2 J10.1 | length 6.8
  Top Layer w0.508: J10.1@8.5,183.92 11.1,181.32 F2.2@11.1,180.5 F2.2@11.1,178.15
NetF3_2: F3.2 J11.1 | length 7.8
  Top Layer w0.508: F3.2@7.518,233.378 7.518,237.398 J11.1@8.5,238.38
  Top Layer w0.762: F3.2@5.295,233.378 F3.2@7.645,233.378
NetF4_2: F4.2 J12.1 | length 7.7
  Top Layer w0.508: F4.2@8.5,205.523 J12.1@8.5,210.88
  Top Layer w0.762: F4.2@6.286,205.387 F4.2@8.636,205.387
NetF5_2: F5.2 J13.1 | length 9.4
  Top Layer w1.016: F5.2@16.15,168.25 F5.2@16.15,170.6
  Top Layer w1.524: J13.1@9,170.54 F5.2@16.09,170.54
NetF6_2: F6.2 J14.1 | length 9.5
  Top Layer w0.762: F6.2@16.199,144.686 F6.2@16.199,147.036
  Top Layer w1.524: J14.1@9.044,147.036 F6.2@16.199,147.036
NetF7_2: F7.2 J17.1 | length 13.1
  Top Layer w0.762: F7.2@409.989,312.678 410.25,312.938 410.25,315.5 J17.1@420.449,315.5
NetF8_2: F8.2 J18.1 | length 12.7
  Top Layer w0.762: F8.2@410.065,142.665 410.065,144.935 J18.1@420.525,144.935
NetF9_2: F9.2 J19.2 | length 18.9
  Top Layer w0.762: F9.2@410,333 F9.2@410,335 416,335 417.712,336.712 420.288,336.712 421.972,335.028 J19.2@425.449,335.028
NetF10_2: F10.2 J20.2 | length 18.9
  Top Layer w0.762: F10.2@410,263 F10.2@410,265 416,265 417.682,266.682 420.318,266.682 422.002,264.998 J20.2@425.475,264.998
NetF11_1: F11.1 J21.2 | length 16.9
  Top Layer w0.762: F11.1@410,165 410.025,164.975 416.025,164.975 417.709,163.291 420.291,163.291 421.975,164.975 J21.2@425.525,164.975
NetF12_1: F12.1 J22.2 | length 16.9
  Top Layer w0.762: F12.1@410,102.5 416.5,102.5 418.184,100.816 419.816,100.816 421.5,102.5 J22.2@425.5,102.5
NetF13_2: F13.2 J23.1 | length 12.7
  Top Layer w0.762: F13.2@410.04,80.19 410.04,82.46 J23.1@420.5,82.46
NetF14_2: F14.2 J24.1 | length 12.7
  Top Layer w0.762: F14.2@410.015,242.688 410.015,244.958 J24.1@420.475,244.958
NetF15_2: F15.2 P337.1 P338.1 P339.1 P340.1 | length 33.3
  Top Layer w1.524: F15.2@160.242,7.62 160.242,11.345 F15.2@160.417,11.52
  Top Layer w2.54: P338.1@137.799,20.836 P337.1@140.339,20.836 P340.1@142.879,20.836 P339.1@145.419,20.836 145.419,18.386 156.185,7.62 F15.2@160.242,7.62
NetF16_2: F16.2 P345.1 P346.1 P347.1 P348.1 | length 25
  Top Layer w1.524: F16.2@82.375,7.53 82.55,7.705 F16.2@82.55,11.43
  Top Layer w2.54: F16.2@82.55,11.43 82.672,11.43 P348.1@92.079,20.836 P347.1@94.619,20.836 P346.1@97.159,20.836 P345.1@99.699,20.836
NetF17_2: F17.2 P353.1 P354.1 P355.1 P356.1 | length 94.9
  Top Layer w1.524: F17.2@267.389,7.62 267.389,11.345 F17.2@267.564,11.52
  Top Layer w2.54: P356.1@183.519,20.836 P355.1@186.059,20.836 P354.1@188.599,20.836 P353.1@191.139,20.836 191.139,18.233 192.049,17.323 234.01,17.323 243.713,7.62 F17.2@267.43,7.62
NetF18_2: F18.2 P369.1 P370.1 P371.1 P372.1 | length 36.7
  Top Layer w1.524: F18.2@106.648,7.62 106.648,11.345 F18.2@106.823,11.52
  Top Layer w2.54: F18.2@106.823,11.52 106.823,13.961 110.058,17.196 124.104,17.196 125.099,18.19 P371.1@125.099,20.836 P370.1@127.639,20.836 P369.1@130.179,20.836 P372.1@132.719,20.836
NetF19_2: F19.2 P377.1 P378.1 P379.1 P380.1 | length 52.5
  Top Layer w1.524: F19.2@213.836,7.62 213.836,11.345 F19.2@214.011,11.52
  Top Layer w2.54: P380.1@170.819,20.836 P379.1@173.359,20.836 P378.1@175.899,20.836 P377.1@178.439,20.836 191.655,7.62 F19.2@213.836,7.62
NetF20_2: F20.2 P385.1 P386.1 P387.1 P388.1 | length 67
  Top Layer w1.524: F20.2@29.035,7.53 29.21,7.705 F20.2@29.21,11.43
  Top Layer w2.54: F20.2@29.21,11.43 48.793,11.43 54.762,17.399 78.181,17.399 79.379,18.597 P388.1@79.379,20.836 P387.1@81.919,20.836 P386.1@84.459,20.836 P385.1@86.999,20.836
NetF98_2: F98.2 J6.3 | length 9.8
  Top Layer w0.508: F98.2@7.65,82.85 F98.2@10,82.85 10,88.92 J6.3@9,89.92
NetF99_1: F99.1 J6.1 | length 7.9
  Top Layer w0.508: J6.1@8.6,100.48 J6.1@9,100.08
  Top Layer w2.54: J6.1@9,100.08 F99.1@9,107.425
NetGMSK1_1A: GMSK1.1A P151.2 | length 18.9
  Top Layer w0.508: GMSK1.1A@312.578,316.9 318.23,316.9 322.178,320.848 322.178,328.544 P151.2@322.178,328.56
NetGMSK1_1B: GMSK1.1B P156.2 | length 15.5
  Top Layer w0.508: GMSK1.1B@363.478,316.95 372.978,326.45 372.978,328.544 P156.2@372.978,328.56
NetGMSK1_1C: GMSK1.1C P161.2 | length 17.4
  Top Layer w0.508: P161.2@327.258,328.56 327.258,328.544 327.258,322.17 GMSK1.1C@335.018,314.41
NetGMSK1_2A: GMSK1.2A P165.2 | length 23.8
  Top Layer w0.508: GMSK1.2A@312.578,314.36 320.387,314.36 324.718,318.691 324.718,328.544 P165.2@324.718,328.56
NetGMSK1_2B: GMSK1.2B P171.2 | length 19.1
  Top Layer w0.508: GMSK1.2B@363.478,314.41 375.518,326.45 375.518,328.544 P171.2@375.518,328.56
NetGMSK1_2C: GMSK1.2C P177.2 | length 21.9
  Top Layer w0.508: P177.2@291.698,328.56 291.698,328.544 291.698,324.48 289.666,322.448 289.666,312.034 292.398,309.302 GMSK1.2C@292.398,308.61
NetGMSK1_3A: GMSK1.3A P152.2 | length 16.7
  Top Layer w0.508: GMSK1.3A@310.038,316.9 310.558,317.42 310.558,318.476 311.66,319.578 315.295,319.578 317.098,321.381 317.098,328.544 P152.2@317.098,328.56
NetGMSK1_3B: GMSK1.3B P157.2 | length 14.5
  Top Layer w0.508: GMSK1.3B@360.938,316.95 360.938,319.298 367.644,326.004 367.644,328.306 P157.2@367.898,328.56
NetGMSK1_3C: GMSK1.3C P162.2 | length 16.3
  Top Layer w0.508: P162.2@332.338,328.56 332.338,328.544 332.338,323.557 336.3,319.595 336.3,316.129 337.558,314.871 GMSK1.3C@337.558,314.41
NetGMSK1_4A: GMSK1.4A P166.2 | length 20.9
  Top Layer w0.508: GMSK1.4A@310.038,314.36 311.32,315.642 311.32,318.16 311.925,318.765 316.514,318.765 319.638,321.889 319.638,328.544 P166.2@319.638,328.56
NetGMSK1_4B: GMSK1.4B P172.2 | length 18.1
  Top Layer w0.508: GMSK1.4B@360.938,314.41 360.938,314.871 362.196,316.129 362.196,318.45 370.438,326.692 370.438,328.544 P172.2@370.438,328.56
NetGMSK1_5A: GMSK1.5A P153.2 | length 13.5
  Top Layer w0.508: GMSK1.5A@307.498,316.9 307.498,318.69 312.018,323.21 312.018,328.544 P153.2@312.018,328.56
NetGMSK1_5B: GMSK1.5B P158.2 | length 13.4
  Top Layer w0.508: GMSK1.5B@358.398,316.95 358.398,320.748 362.818,325.168 362.818,328.544 P158.2@362.818,328.56
NetGMSK1_5C: GMSK1.5C P163.2 | length 15.3
  Top Layer w0.508: P163.2@337.418,328.56 337.418,328.544 337.418,325.081 338.84,323.659 338.84,316.129 340.098,314.871 GMSK1.5C@340.098,314.41
NetGMSK1_6A: GMSK1.6A P167.2 | length 17.1
  Top Layer w0.508: GMSK1.6A@307.498,314.36 308.78,315.642 308.78,317.776 314.558,323.554 314.558,328.544 P167.2@314.558,328.56
NetGMSK1_6B: GMSK1.6B P173.2 | length 17
  Top Layer w0.508: GMSK1.6B@358.398,314.41 358.398,314.871 359.656,316.129 359.656,319.593 365.358,325.295 365.358,328.544 P173.2@365.358,328.56
NetGMSK1_7A: GMSK1.7A P154.2 | length 12.5
  Top Layer w0.508: GMSK1.7A@304.958,316.9 304.958,319.96 306.938,321.94 306.938,328.544 P154.2@306.938,328.56
NetGMSK1_7B: GMSK1.7B P159.2 | length 12.4
  Top Layer w0.508: GMSK1.7B@355.858,316.95 355.858,322.018 357.738,323.898 357.738,328.544 P159.2@357.738,328.56
NetGMSK1_7C: GMSK1.7C P164.2 | length 15.1
  Top Layer w0.508: P164.2@342.498,328.56 342.498,328.544 342.498,318.889 341.38,317.771 341.38,316.129 342.638,314.871 GMSK1.7C@342.638,314.41
NetGMSK1_8A: GMSK1.8A P168.2 | length 16.1
  Top Layer w0.508: GMSK1.8A@304.958,314.36 306.24,315.642 306.24,318.51 309.478,321.748 309.478,328.544 P168.2@309.478,328.56
NetGMSK1_8B: GMSK1.8B P174.2 | length 16
  Top Layer w0.508: GMSK1.8B@355.858,314.41 355.858,314.871 357.116,316.129 357.116,321.625 360.278,324.787 360.278,328.544 P174.2@360.278,328.56
NetGMSK1_8C: GMSK1.8C P178.2 P179.2 P180.2 P181.2 P182.2 P183.2 P184.2 | length 171.3
  Top Layer w0.508: GMSK1.8C@292.398,306.07 297.032,310.704 297.032,320.924 294.238,323.718 294.238,328.544 P178.2@294.238,328.56 ; P180.2@297.032,328.306 297.032,326.599 299.878,323.753 GMSK1.8C@299.878,316.9 ; P181.2@329.798,328.56 329.798,328.544 329.798,322.17 GMSK1.8C@335.018,316.95 ; P182.2@334.878,328.56 334.878,328.544 334.878,325.208 337.558,322.528 GMSK1.8C@337.558,316.95 ; P183.2@339.958,328.56 340.098,328.42 GMSK1.8C@340.098,316.95 ; GMSK1.8C@342.638,316.95 345.038,319.35 345.038,328.544 P184.2@345.038,328.56 ; P179.2@347.578,328.56 347.832,328.306 347.832,326.599 350.778,323.653 GMSK1.8C@350.778,316.95
  DELETEME w0.508: GMSK1.8C@292.398,306.07 297.572,311.244 ; GMSK1.8C@299.878,316.9 297.572,314.594 297.572,311.244 ; GMSK1.8C@350.778,316.95 GMSK1.8C@342.638,316.95 GMSK1.8C@340.098,316.95 GMSK1.8C@337.558,316.95 GMSK1.8C@335.018,316.95 332.684,316.95 326.978,311.244 297.572,311.244
NetGMSK1_9A: GMSK1.9A P155.2 | length 11.9
  Top Layer w0.508: P155.2@301.858,328.56 302.112,328.306 302.112,326.599 302.418,326.293 GMSK1.9A@302.418,316.9
NetGMSK1_9B: GMSK1.9B P160.2 | length 11.9
  Top Layer w0.508: P160.2@352.658,328.56 352.912,328.306 352.912,326.599 353.318,326.193 GMSK1.9B@353.318,316.95
NetGMSK1_10A: GMSK1.10A P169.2 | length 15
  Top Layer w0.508: GMSK1.10A@302.418,314.36 303.7,315.642 303.7,319.78 304.398,320.478 304.398,328.544 P169.2@304.398,328.56
NetGMSK1_10B: GMSK1.10B P175.2 | length 14.9
  Top Layer w0.508: GMSK1.10B@353.318,314.41 354.6,315.692 354.6,322.411 355.096,322.907 355.096,328.458 P175.2@355.198,328.56
NetGMSK1_12A: GMSK1.12A P170.2 | length 15.5
  Top Layer w0.508: P170.2@299.318,328.56 299.572,328.306 299.572,326.599 301.136,325.035 301.136,315.618 GMSK1.12A@299.878,314.36
NetGMSK1_12B: GMSK1.12B P176.2 | length 15.6
  Top Layer w0.508: P176.2@350.118,328.56 350.372,328.306 350.372,326.599 352.17,324.801 352.17,317.881 352.06,317.771 352.06,315.692 GMSK1.12B@350.778,314.41
NetJ15_1: J15.1 P185.2 | length 10.9
  Top Layer w0.254: J15.1@5.292,293.302 8.348,293.302 8.899,292.751 8.899,292.226 12.903,288.222 P185.2@12.903,287.336
NetJ15_2: J15.2 P187.2 | length 9
  Top Layer w0.254: J15.2@5.292,295.8 9.518,295.8 P187.2@12.903,292.416
NetJ15_3: J15.3 P189.2 | length 6
  Top Layer w0.508: J15.3@7.832,297.112 7.845,297.125 10.733,297.125 P189.2@12.903,294.956
NetJ15_4: J15.4 P191.2 | length 8
  Top Layer w0.508: J15.4@5.292,298.382 5.299,298.375 11.625,298.375 12.504,297.496 P191.2@12.903,297.496
NetJ15_5: J15.5 P193.2 | length 8.3
  Top Layer w0.508: J15.5@5.292,300.922 5.368,300.998 8.498,300.998 10.076,302.576 P193.2@12.903,302.576
NetJ15_6: J15.6 P186.2 | length 9.3
  Top Layer w0.254: J15.6@7.832,292.032 7.832,289.866 P186.2@12.903,284.796
NetJ15_7: J15.7 P188.2 | length 7
  Top Layer w0.254: J15.7@7.832,294.572 12.528,289.876 P188.2@12.903,289.876
NetJ15_8: J15.8 P190.2 | length 5.9
  Top Layer w0.508: J15.8@8.216,300.036 J15.8@7.832,299.652 7.959,299.525 12.392,299.525 P190.2@12.903,300.036
NetJ15_9: J15.9 P192.2 | length 6.3
  Top Layer w0.508: J15.9@7.832,302.192 10.756,305.116 P192.2@12.903,305.116
NetJ16_1: J16.1 P194.2 | length 8.9
  Top Layer w0.254: J16.1@5.292,262.528 5.32,262.5 9.1,262.5 12.204,259.396 P194.2@12.903,259.396
NetJ16_2: J16.2 P196.2 | length 7.9
  Top Layer w0.254: J16.2@5.292,265.068 5.31,265.05 11.65,265.05 12.224,264.476 P196.2@12.903,264.476
NetJ16_3: J16.3 P198.2 | length 5.4
  Top Layer w0.508: J16.3@7.832,266.338 8.498,266.338 9.175,267.016 P198.2@12.903,267.016
NetJ16_4: J16.4 P200.2 | length 7.5
  Top Layer w0.254: 6.1,267.775 10.15,267.775 11.931,269.556 P200.2@12.903,269.556
NetJ16_5: J16.5 P202.2 | length 9.5
  Top Layer w0.508: J16.5@5.292,270.148 8.415,270.148 P202.2@12.903,274.636
NetJ16_6: J16.6 P195.2 | length 6.9
  Top Layer w0.254: J16.6@7.832,261.258 12.235,256.856 P195.2@12.903,256.856
NetJ16_7: J16.7 P197.2 | length 5.9
  Top Layer w0.254: J16.7@7.832,263.798 7.859,263.825 10.85,263.825 12.739,261.936 P197.2@12.903,261.936
NetJ16_8: J16.8 P199.2 | length 6.4
  Top Layer w0.508: J16.8@7.832,268.878 9.128,268.878 12.346,272.096 P199.2@12.903,272.096
NetJ16_9: J16.9 P201.2 | length 8.4
  Top Layer w0.254: J16.9@7.832,271.418 7.6,271.65 8.125,271.65 12.903,276.428 P201.2@12.903,277.176
NetJ25_2: J25.2 P449.1 | length 5.1
  Top Layer w0.508: P449.1@257.128,194.42 J25.2@257.128,199.5
NetJ26_2: J26.2 P455.1 | length 4.1
  Top Layer w0.508: P455.1@379.104,147.652 J26.2@379.104,151.732
NetJ35_1: J35.1 U18.2 | length 9.3
  Top Layer w0.152: J35.1@138,310 140,312 144.154,312 145.52,313.366 U18.2@145.52,313.75
NetJ35_2: J35.2 U18.3 | length 8.3
  Top Layer w0.152: J35.2@140.54,310 142.21,311.67 145.554,311.67 146.79,312.906 U18.3@146.79,313.75
NetJ35_3: J35.3 U18.4 | length 7
  Top Layer w0.152: J35.3@143.08,310 144.42,311.34 146.494,311.34 148.06,312.906 U18.4@148.06,313.75
NetJ35_4: J35.4 U18.5 | length 5.8
  Top Layer w0.152: J35.4@145.62,310 146.516,310.896 147.32,310.896 149.33,312.906 U18.5@149.33,313.75
NetJ35_5: J35.5 U18.6 | length 4.8
  Top Layer w0.152: J35.5@148.16,310 150.6,312.44 U18.6@150.6,313.75
NetJ35_6: J35.6 U18.7 | length 4.2
  Top Layer w0.152: J35.6@150.7,310 151.87,311.17 U18.7@151.87,313.75
NetJ35_7: J35.7 U18.8 | length 3.8
  Top Layer w0.152: U18.8@153.14,313.75 153.24,313.65 J35.7@153.24,310
NetJ35_8: J35.8 U18.9 | length 4.3
  Top Layer w0.152: U18.9@154.41,313.75 154.41,311.37 J35.8@155.78,310
NetJ36_1: J36.1 U19.2 | length 9.9
  Top Layer w0.152: J36.1@158.28,310 160.376,312.096 165.665,312.096 166.27,312.701 U19.2@166.27,313.5
NetJ36_2: J36.2 U19.3 | length 8.7
  Top Layer w0.152: J36.2@160.82,310 162.586,311.766 166.732,311.766 167.54,312.574 U19.3@167.54,313.5
NetJ36_3: J36.3 U19.4 | length 7.4
  Top Layer w0.152: J36.3@163.36,310 164.796,311.436 167.545,311.436 168.81,312.701 U19.4@168.81,313.5
NetJ36_4: J36.4 U19.5 | length 6.2
  Top Layer w0.152: J36.4@165.9,310 167.005,311.105 168.611,311.105 170.08,312.574 U19.5@170.08,313.5
NetJ36_5: J36.5 U19.6 | length 4.7
  Top Layer w0.152: J36.5@168.44,310 171.35,312.91 U19.6@171.35,313.5
NetJ36_6: J36.6 U19.7 | length 4.2
  Top Layer w0.152: J36.6@170.98,310 172.62,311.64 U19.7@172.62,313.5
NetJ36_7: J36.7 U19.8 | length 3.7
  Top Layer w0.152: J36.7@173.52,310 173.52,313.13 U19.8@173.89,313.5
NetJ36_8: J36.8 U19.9 | length 3.9
  Top Layer w0.152: U19.9@175.16,313.5 175.16,310.9 J36.8@176.06,310
NetLDO1_EN1: LDO1.EN1 P518.2 | length 8.4
  Top Layer w0.508: P518.2@180.658,163.94 180.674,163.94 182.96,163.94 186.294,160.606 LDO1.EN1@187.671,160.606
NetLDO1_EN2: LDO1.EN2 P521.2 | length 7.9
  Top Layer w0.508: P521.2@180.658,174.1 180.674,174.1 183.722,174.1 185.786,172.036 LDO1.EN2@187.671,172.036
NetLDO1_EN3: LDO1.EN3 P524.2 | length 7.3
  Top Layer w0.508: P524.2@180.658,184.26 180.674,184.26 183.849,184.26 184.643,183.466 LDO1.EN3@187.671,183.466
